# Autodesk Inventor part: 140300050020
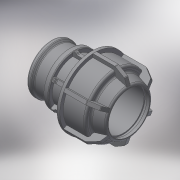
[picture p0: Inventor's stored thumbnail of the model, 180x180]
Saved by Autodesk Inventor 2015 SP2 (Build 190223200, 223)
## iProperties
Created: 2017-08
Part Number: 140300050020
Material: Generic
Description: PLASSON L.14 FEMALE ADAPTOR (SILVER) 50-2"
Document SubType Name: Modeling
Designer: KIM
Density: 1 g/cm^3
Appearance: Default
Author: KIM
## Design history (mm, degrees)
derived "140300.ipt"
feature "Solid1::140300.ipt"
tag "TaggingFeature1"
body "Solid1"
other parameters: "d2" = 82, "d4" = 15 deg, "d5" = 54.12, "d6" = 17.8596, "d9" = 56.656, "d10" = 92, "d11" = 73.6528, "d12" = 67.9872, "d13" = 79.3184, "d16" = 51, "d17" = 4.1, "d18" = 112, "d19" = 9, "d20" = 135 deg, "d21" = 9, "d22" = 67.9872, "d24" = 4.1, "d25" = 82.8, "d26" = 69, "d27" = 4.1, "d28" = 135 deg, "d29" = 2.46, "d31" = 2.5, "d44" = 1, "d45" = 1.5, "d46" = 150 deg, "d49" = 4.6, "d50" = 0, "d51" = 0.92, "d52" = 1.84, "d53" = 45 deg, "d55" = 9.752, "d56" = 4.6, "d57" = 0, "d58" = 1.5, "d61" = 360 deg, "G_" = 56.656, "E_" = 92, "H_" = 112, "l_" = 82, "d54" = 24.38
